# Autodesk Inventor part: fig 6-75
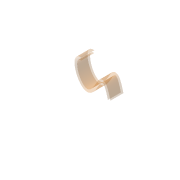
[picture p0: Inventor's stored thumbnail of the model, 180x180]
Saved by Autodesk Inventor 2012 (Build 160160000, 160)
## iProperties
Shininess: 64.0
Length Units: 11269
Angle Units: 11279
Time Units: 11290
Mass Units: 11283
Length Display Precision: 3
Angle Display Precision: 2
Compacted: True
Part Number: fig 6-75
Document SubType Name: Modeling
Created: 2002-12
Designer: deepak
Density: 1 g/cm^3
Material: Default
Density: 0.0
Volumn: 0.0
Area: 0.0
PropertySet Name: Model Information
Control State: 0
Master: False
Checked Out: False
Author: deepak
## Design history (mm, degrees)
sketch "Sketch1"
  geometry: 5 further points
  constraints: 5 other
extrude_surface "ExtrusionSrf1" sketch "Sketch1" dims "d0" = 20, "d1" = 0
feature "OffsetSrf2" dims "d8" = 4, "d9" = 4
body "Solid1"
body "Srf1"
body "Srf2"
